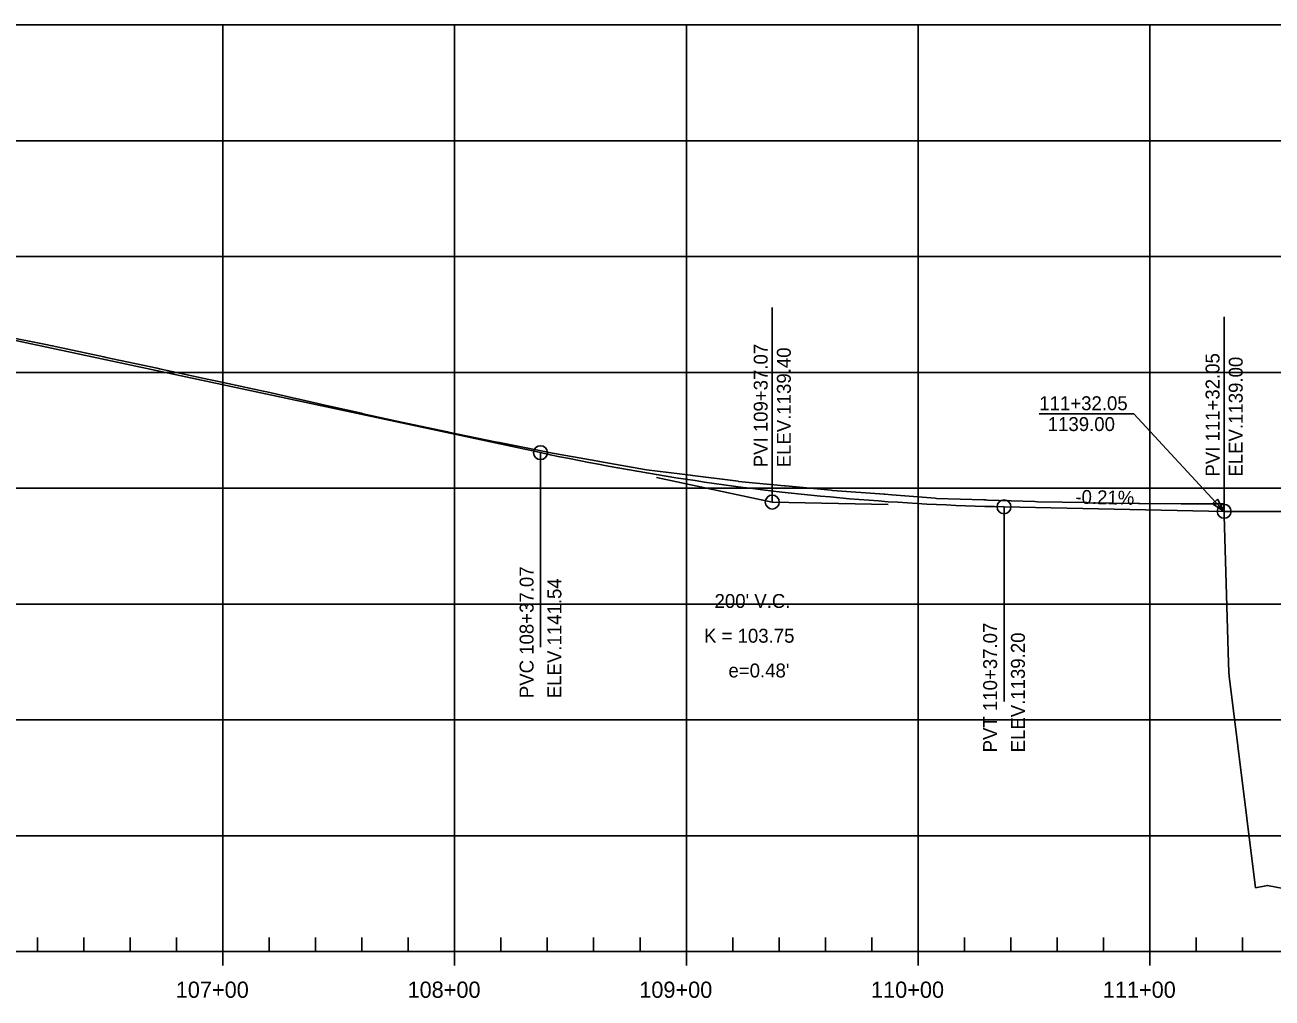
# Model space of a CAD drawing. Extents: x 688474 to 694748, y 765018 to 767373.
# Drawn here: x 691570 to 692108, y 766506 to 766926 of the extents above; entities that cross this region are included whole.
import ezdxf

# ---------------------------------------------------------------- set-up
doc = ezdxf.new("R2010")
doc.units = 0
for name, color, linetype in [('30', 7, 'Continuous'), ('37', 7, 'Continuous'), ('R_Exist Surface', 7, 'Continuous'), ('R_Horz Alg Annot', 7, 'Continuous'), ('R_Vert Alg', 7, 'Continuous'), ('R_Vert Alg Annot', 7, 'Continuous')]:
    doc.layers.add(name, color=color, linetype=linetype)

msp = doc.modelspace()

# ---------------------------------------------------------------- linework, layer by layer
at = {"layer": '37'}
for p, q in [((690955.19, 766926.49), (693355.19, 766926.49)), ((690955.19, 766926.49), (693355.19, 766926.49)), ((691655.19, 766526.49), (691655.19, 766926.49)), ((691755.19, 766526.49), (691755.19, 766926.49)), ((691855.19, 766526.49), (691855.19, 766926.49)), ((691955.19, 766526.49), (691955.19, 766926.49)), ((692055.19, 766526.49), (692055.19, 766926.49)), ((690955.19, 766876.49), (693355.19, 766876.49)), ((690955.19, 766826.49), (693355.19, 766826.49)), ((690955.19, 766776.49), (693355.19, 766776.49)), ((690955.19, 766726.49), (693355.19, 766726.49)), ((690955.19, 766676.49), (693355.19, 766676.49)), ((690955.19, 766626.49), (693355.19, 766626.49)), ((690955.19, 766576.49), (693355.19, 766576.49)), ((691575.19, 766526.49), (691575.19, 766532.49)), ((691595.19, 766526.49), (691595.19, 766532.49)), ((691615.19, 766526.49), (691615.19, 766532.49)), ((691635.19, 766526.49), (691635.19, 766532.49)), ((691675.19, 766526.49), (691675.19, 766532.49)), ((691695.19, 766526.49), (691695.19, 766532.49)), ((691715.19, 766526.49), (691715.19, 766532.49)), ((691735.19, 766526.49), (691735.19, 766532.49)), ((691775.19, 766526.49), (691775.19, 766532.49)), ((691795.19, 766526.49), (691795.19, 766532.49)), ((691815.19, 766526.49), (691815.19, 766532.49)), ((691835.19, 766526.49), (691835.19, 766532.49)), ((691875.19, 766526.49), (691875.19, 766532.49)), ((691895.19, 766526.49), (691895.19, 766532.49)), ((691915.19, 766526.49), (691915.19, 766532.49)), ((691935.19, 766526.49), (691935.19, 766532.49)), ((691975.19, 766526.49), (691975.19, 766532.49)), ((691995.19, 766526.49), (691995.19, 766532.49)), ((692015.19, 766526.49), (692015.19, 766532.49)), ((692035.19, 766526.49), (692035.19, 766532.49)), ((692075.19, 766526.49), (692075.19, 766532.49)), ((692095.19, 766526.49), (692095.19, 766532.49)), ((690955.19, 766526.49), (693355.19, 766526.49)), ((691655.19, 766520.49), (691655.19, 766526.49)), ((691755.19, 766520.49), (691755.19, 766526.49)), ((691855.19, 766520.49), (691855.19, 766526.49)), ((691955.19, 766520.49), (691955.19, 766526.49)), ((692055.19, 766520.49), (692055.19, 766526.49))]:
    msp.add_line(p, q, dxfattribs=at)
at = {"layer": 'R_Exist Surface'}
msp.add_line((692007.46, 766758.67), (692042.25, 766758.67), dxfattribs=at)
for points in [[(691559.29, 766792.44), (691579.55, 766788.37), (691580.73, 766788.16), (691581.57, 766788), (691603.87, 766783.2), (691604.8, 766782.98), (691626.79, 766778.25), (691627.85, 766777.99), (691649.13, 766773.45), (691650.61, 766773.13), (691652.06, 766772.82), (691673.37, 766768.27), (691674.11, 766768.12), (691687.26, 766765.12), (691687.99, 766764.97), (691701.15, 766761.97), (691701.88, 766761.81), (691715.04, 766758.82), (691715.76, 766758.66), (691728.92, 766755.66), (691729.58, 766755.51), (691752.13, 766750.76), (691752.53, 766750.67), (691772.72, 766746.57), (691773.61, 766746.4), (691774.5, 766746.23), (691794.66, 766742.15), (691795.89, 766741.94), (691816.33, 766738.3), (691817.76, 766738.06), (691838.02, 766734.46), (691857.05, 766732.06), (691857.86, 766731.95), (691877.59, 766729.47), (691877.68, 766729.45), (691897.59, 766727.54), (691897.99, 766727.49), (691917.61, 766725.6), (691918.29, 766725.52), (691940.6, 766723.9), (691940.69, 766723.89), (691940.79, 766723.89), (691943.9, 766723.66), (691962.55, 766722.15), (691963.14, 766722.11), (691983.59, 766721.42), (691984.37, 766721.41), (691985.15, 766721.39), (692005.59, 766720.71), (692006.68, 766720.67), (692027.95, 766720.28), (692028.81, 766720.24), (692050.3, 766719.86), (692050.82, 766719.88), (692068.72, 766719.78), (692087.12, 766719.68), (692087.13, 766719.68), (692087.13, 766719.53), (692089.11, 766651.16), (692089.2, 766647.29), (692089.41, 766645.32), (692100.79, 766553.99), (692105.97, 766555), (692116.46, 766552.91)], [(692087.24, 766716.49), (692048.25, 766758.67), (692042.25, 766758.67)]]:
    msp.add_lwpolyline(points, dxfattribs=at)
msp.add_lwpolyline([(692087.24, 766716.49), (692082.22, 766719.77), (692084.35, 766721.75)], close=True, dxfattribs=at)
at = {"layer": 'R_Vert Alg'}
for p, q in [((690955.19, 766920.47), (691792.26, 766741.85)), ((691842.26, 766731.18), (691892.26, 766720.51)), ((691892.26, 766720.51), (691942.26, 766719.48)), ((691992.26, 766718.45), (692087.24, 766716.49)), ((692087.24, 766716.49), (692272.04, 766716.49))]:
    msp.add_line(p, q, dxfattribs=at)
msp.add_lwpolyline([(691792.26, 766741.85), (691796.43, 766740.96), (691800.59, 766740.1), (691804.76, 766739.25), (691808.93, 766738.42), (691813.09, 766737.61), (691817.26, 766736.81), (691821.43, 766736.03), (691825.59, 766735.27), (691829.76, 766734.52), (691833.93, 766733.79), (691838.09, 766733.08), (691842.26, 766732.38), (691846.43, 766731.7), (691850.59, 766731.04), (691854.76, 766730.39), (691858.93, 766729.76), (691863.09, 766729.15), (691867.26, 766728.55), (691871.43, 766727.97), (691875.59, 766727.41), (691879.76, 766726.86), (691883.93, 766726.33), (691888.09, 766725.82), (691896.43, 766724.85), (691900.59, 766724.38), (691904.76, 766723.94), (691908.93, 766723.51), (691913.09, 766723.1), (691917.26, 766722.7), (691921.43, 766722.32), (691925.59, 766721.96), (691929.76, 766721.62), (691933.93, 766721.29), (691938.09, 766720.98), (691942.26, 766720.68), (691946.43, 766720.4), (691950.59, 766720.14), (691954.76, 766719.9), (691958.93, 766719.67), (691963.09, 766719.46), (691967.26, 766719.26), (691971.43, 766719.08), (691975.59, 766718.92), (691979.76, 766718.78), (691983.93, 766718.65), (691988.09, 766718.54), (691992.26, 766718.45)], dxfattribs=at)
for centre in [(691792.26, 766741.85), (691892.26, 766720.51), (691992.26, 766718.45), (692087.24, 766716.49)]:
    msp.add_circle(centre, 3, dxfattribs=at)
at = {"layer": 'R_Vert Alg Annot'}
for p, q in [((691892.26, 766720.51), (691892.26, 766804.51)), ((692087.24, 766716.49), (692087.24, 766800.49)), ((691792.26, 766741.85), (691792.26, 766657.85)), ((691992.26, 766718.45), (691992.26, 766634.45))]:
    msp.add_line(p, q, dxfattribs=at)

# ---------------------------------------------------------------- texts
at = {"layer": '30'}
for s, p in [('107+00', (691634.88, 766506.49)), ('108+00', (691734.88, 766506.49)), ('109+00', (691834.88, 766506.49)), ('110+00', (691934.88, 766506.49)), ('111+00', (692034.88, 766506.49))]:
    msp.add_text(s, height=7, dxfattribs=at).set_placement(p)
at = {"layer": 'R_Horz Alg Annot'}
for s, p in [('111+32.05', (692007.46, 766760.17)), ('1139.00', (692011.12, 766751.17))]:
    msp.add_text(s, height=6, dxfattribs=at).set_placement(p)
at = {"layer": 'R_Vert Alg Annot'}
for s, rotation, p in [('PVI 109+37.07', 90, (691890.26, 766735.51)), ('ELEV.1139.40', 90, (691900.26, 766735.51)), ('PVI 111+32.05', 90, (692085.24, 766731.49)), ('ELEV.1139.00', 90, (692095.24, 766731.49)), ('-0.21%', 358.8188, (692022.99, 766719.81)), ('PVC 108+37.07', 90, (691789.26, 766635.85)), ('ELEV.1141.54', 90, (691801.26, 766635.85)), ('PVT 110+37.07', 90, (691989.26, 766612.45)), ('ELEV.1139.20', 90, (692001.26, 766612.45))]:
    msp.add_text(s, height=6, rotation=rotation, dxfattribs=at).set_placement(p)
for s, p in [("200' V.C.", (691867.36, 766674.8)), ('K = 103.75', (691862.8, 766659.8)), ("e=0.48'", (691873.36, 766644.8))]:
    msp.add_text(s, height=6, dxfattribs=at).set_placement(p)

doc.saveas('drawing.dxf')
